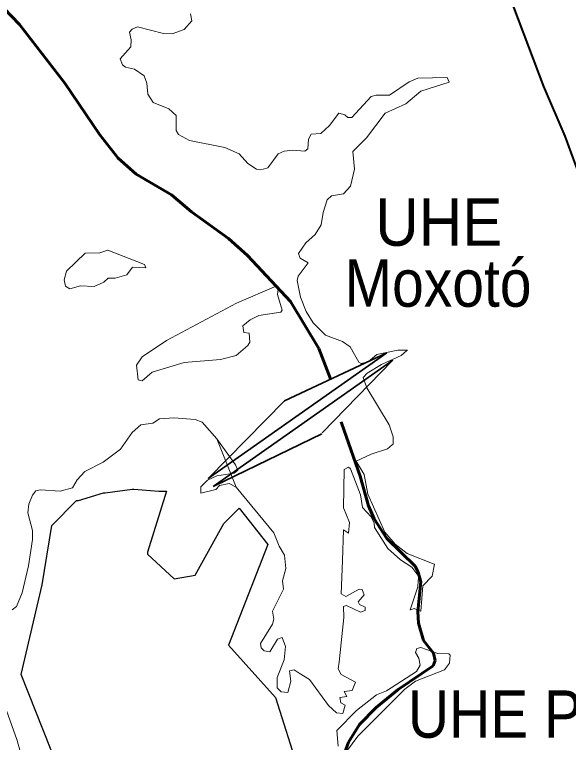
# Model space of a CAD drawing. Extents: x 553962 to 842807, y 8883888 to 9032388.
# Drawn here: x 584093 to 589939, y 8960655 to 8968341 of the extents above; entities that cross this region are included whole.
import ezdxf
from ezdxf.enums import TextEntityAlignment as Align

# ---------------------------------------------------------------- set-up
doc = ezdxf.new("R2010")
doc.units = 0
doc.header["$LTSCALE"] = 200
doc.linetypes.add('LONG_DASH_SHORT_DASH', pattern=[9.9, 6, -1.2, 1.5, -1.2])
for name, color, linetype, lineweight in [('12', 7, 'Continuous', 25), ('21', 7, 'Continuous', 25), ('25', 7, 'Continuous', 13), ('7', 7, 'LONG_DASH_SHORT_DASH', 60)]:
    doc.layers.add(name, color=color, linetype=linetype, lineweight=lineweight)
doc.layers.add('42', color=7, linetype='Continuous')

msp = doc.modelspace()

# ---------------------------------------------------------------- linework, layer by layer
at = {"layer": '12', "lineweight": 40}
msp.add_lwpolyline([(589251, 8968710.7), (589674.6, 8967582.3), (589899.5, 8967058.9), (590052.2, 8966645.4), (590154.6, 8966267.7), (590247.4, 8965995.5), (590238.8, 8965878.8), (590381.4, 8965077.2), (590437.7, 8964620.9), (590556.9, 8963909.5), (590712.3, 8962804.7), (590781.8, 8962609.4), (591396.4, 8961227.9)], dxfattribs=at)
at = {"layer": '21'}
msp.add_lwpolyline([(584626.8, 8960201.4), (584162.8, 8961372.1), (584384.7, 8962320.7), (584485.6, 8962946.4), (584747.9, 8963208.8), (584768.1, 8963208.8), (585030.4, 8963289.5), (585050.6, 8963289.5), (585333, 8963329.9), (585353.2, 8963329.9), (585615.5, 8963309.7), (585655.9, 8963309.7), (585676, 8963309.7), (585696.2, 8963309.7), (585494.5, 8962663.8), (585494.5, 8962643.7), (585776.9, 8962381.3), (585998.9, 8962421.6), (586301.5, 8962966.6), (586463, 8963128.1), (586765.6, 8962744.6), (586351.3, 8961682.2), (586846.3, 8961129.9), (587088.5, 8960362.9)], dxfattribs=at)
at = {"layer": '25', "lineweight": 35}
for p, q in [((588022.6, 8964770.6), (586135.6, 8963442.6)), ((586940.7, 8964263.4), (588022.6, 8964770.6)), ((588084.7, 8964692), (586189.9, 8963358.5)), ((587339.3, 8963925.5), (588084.7, 8964692)), ((586940.7, 8964263.4), (586135.6, 8963442.6)), ((586189.9, 8963358.5), (587335.7, 8963913.8))]:
    msp.add_line(p, q, dxfattribs=at)
at = {"layer": '25'}
for points in [[(585950.2, 8968348.5), (585965.4, 8968274.1), (585883, 8968184.3), (585757.4, 8968137.5), (585664, 8968141.7), (585392.1, 8968211.7), (585332.8, 8968188.5), (585307.1, 8968156.3), (585324, 8968076.1), (585319.8, 8967999.4)], [(585950.2, 8968348.5), (585965.4, 8968274.1), (585883, 8968184.3), (585757.4, 8968137.5), (585664, 8968141.7), (585392.1, 8968211.7), (585332.8, 8968188.5), (585307.1, 8968156.3), (585324, 8968076.1), (585319.8, 8967999.4)], [(585319.8, 8967999.4), (585209.4, 8967874), (585230.7, 8967810.4), (585264.6, 8967784.9), (585358.3, 8967763.5), (585460, 8967695.5), (585487.7, 8967616.8), (585500.5, 8967502.3), (585557.8, 8967413.1), (585721.3, 8967347.2), (585797.8, 8967276.9), (585799.9, 8967116.4), (585821.7, 8967075), (585940.4, 8967011.6), (586314, 8966937.2), (586464.8, 8966869.3), (586554.2, 8966767.2), (586645.4, 8966710), (586692.1, 8966701.5), (586766.2, 8966722.7), (586877, 8966869.2), (586938.3, 8966898.9), (587031.7, 8966909.6), (587155.3, 8966899.2), (587187, 8966922.6), (587195.6, 8967026.5), (587225.2, 8967079.4), (587325, 8967083.9), (587416.4, 8967171), (587516.5, 8967298.4), (587577.2, 8967281.7), (587609.8, 8967253.9), (587652.2, 8967256), (587856.2, 8967474.6), (587908.7, 8967491.8), (588049.3, 8967489.5), (588259.2, 8967631.5), (588349.7, 8967670.3), (588657.3, 8967677.5), (588667.8, 8967651.8)], [(585319.8, 8967999.4), (585209.4, 8967874), (585230.7, 8967810.4), (585264.6, 8967784.9), (585358.3, 8967763.5), (585460, 8967695.5), (585487.7, 8967616.8), (585500.5, 8967502.3), (585557.8, 8967413.1), (585721.3, 8967347.2), (585797.8, 8967276.9), (585799.9, 8967116.4), (585821.7, 8967075), (585940.4, 8967011.6), (586314, 8966937.2), (586464.8, 8966869.3), (586554.2, 8966767.2), (586645.4, 8966710), (586692.1, 8966701.5), (586766.2, 8966722.7), (586877, 8966869.2), (586938.3, 8966898.9), (587031.7, 8966909.6), (587155.3, 8966899.2), (587187, 8966922.6), (587195.6, 8967026.5), (587225.2, 8967079.4), (587325, 8967083.9), (587416.4, 8967171), (587516.5, 8967298.4), (587577.2, 8967281.7), (587609.8, 8967253.9), (587652.2, 8967256), (587856.2, 8967474.6), (587908.7, 8967491.8), (588049.3, 8967489.5), (588259.2, 8967631.5), (588349.7, 8967670.3), (588657.3, 8967677.5), (588667.8, 8967651.8)], [(588667.8, 8967651.8), (588678.2, 8967626.5), (588381.1, 8967532.1), (588221.7, 8967398.4), (588005.1, 8967300.6), (587807.3, 8967041.3), (587663.1, 8966894.9), (587682, 8966707.8), (587637.4, 8966529.4), (587563.2, 8966446.7), (587438, 8966427.4), (587392.7, 8966384.2), (587348.6, 8966249.6), (587329.2, 8966121.3), (587265.6, 8966019.6), (587165.8, 8965932.5), (587089.5, 8965818), (587106.5, 8965769), (587193.3, 8965719.9), (587087.2, 8965577.5), (587074.5, 8965534.6), (587110.7, 8965356.6), (587170.4, 8965207.5), (587244.3, 8965087.2), (587376.1, 8964957.5), (587554.3, 8964887.4), (587635.2, 8964832.1), (587726.7, 8964670.8), (587750.6, 8964658), (587826.4, 8964675), (587917.9, 8964751.3), (588138.8, 8964796.3), (588239.8, 8964798.6), (588239.8, 8964798.6), (588231, 8964790.9)], [(588667.8, 8967651.8), (588678.2, 8967626.5), (588381.1, 8967532.1), (588221.7, 8967398.4), (588005.1, 8967300.6), (587807.3, 8967041.3), (587663.1, 8966894.9), (587682, 8966707.8), (587637.4, 8966529.4), (587563.2, 8966446.7), (587438, 8966427.4), (587392.7, 8966384.2), (587348.6, 8966249.6), (587329.2, 8966121.3), (587265.6, 8966019.6), (587165.8, 8965932.5), (587089.5, 8965818), (587106.5, 8965769), (587193.3, 8965719.9), (587087.2, 8965577.5), (587074.5, 8965534.6), (587110.7, 8965356.6), (587170.4, 8965207.5), (587244.3, 8965087.2), (587376.1, 8964957.5), (587554.3, 8964887.4), (587635.2, 8964832.1), (587678.5, 8964757.6)], [(588231, 8964790.9), (588174.2, 8964740.5), (587964.7, 8964647.4), (587813.9, 8964556), (587773.6, 8964509.6), (587809.5, 8964400.9), (588045.3, 8964009.8), (588090.5, 8963883.4), (588087.9, 8963805.8), (588079.5, 8963798.7)], [(587773.6, 8964509.6), (587809.5, 8964400.9), (588045.3, 8964009.8), (588090.5, 8963883.4), (588087.9, 8963805.8), (588079.5, 8963798.7)], [(587098.4, 8961386.8), (587045, 8961420.4), (586993.8, 8961411.8), (587008.6, 8961303.5), (586976.2, 8961182.7), (586906.7, 8961189.1), (586864.3, 8961233.5), (586864.2, 8961341.7), (586938.6, 8961529.2), (586953.1, 8961669.7), (586916.8, 8961762.6), (586868.3, 8961747.5), (586787.2, 8961611.7), (586725.9, 8961622.5), (586694.3, 8961654.3), (586687.9, 8961700.7), (586815.2, 8961902.8), (586830.2, 8961956.5), (586815.4, 8962043.2), (586930, 8962273.3), (586921.5, 8962361.5), (586957.6, 8962493.3), (586943, 8962632.7), (586885.4, 8962727), (586830, 8962867.4), (586432.9, 8963349.4), (586358.6, 8963389.7), (586254.6, 8963368.5), (586216.2, 8963326.1), (586059.1, 8963288.1), (586058.9, 8963353.2), (586131.1, 8963423.6), (586229.2, 8963469.6), (586410.8, 8963500), (586449.8, 8963530), (586424.4, 8963587.3), (586226.9, 8963861.3), (586073.9, 8964035.5), (585999.3, 8964065.2), (585774.7, 8964084.4), (585623.6, 8964071.6), (585553.5, 8964025), (585426.1, 8964010), (585334.9, 8963929.5), (585211.3, 8963752.8), (585026.9, 8963615.1), (584835.5, 8963515.1), (584755, 8963428.2), (584703.5, 8963345.2), (584575.7, 8963306.9), (584575.7, 8963306.9), (584367.9, 8963323.8), (584319.4, 8963311.1), (584283.8, 8963267.3), (584244.9, 8963172.8), (584232.2, 8963079.6), (584283.2, 8962892.7), (584283.2, 8962799.2), (584240.7, 8962518.8), (584172.1, 8962236.3), (584113.2, 8962091.9), (584066.4, 8962055.5)], [(587098.4, 8961386.8), (587045, 8961420.4), (586993.8, 8961411.8), (587008.6, 8961303.5), (586976.2, 8961182.7), (586906.7, 8961189.1), (586864.3, 8961233.5), (586864.2, 8961341.7), (586938.6, 8961529.2), (586953.1, 8961669.7), (586916.8, 8961762.6), (586868.3, 8961747.5), (586787.2, 8961611.7), (586725.9, 8961622.5), (586694.3, 8961654.3), (586687.9, 8961700.7), (586815.2, 8961902.8), (586830.2, 8961956.5), (586815.4, 8962043.2), (586930, 8962273.3), (586921.5, 8962361.5), (586957.6, 8962493.3), (586943, 8962632.7), (586885.4, 8962727), (586830, 8962867.4), (586432.9, 8963349.4), (586226.9, 8963861.3), (586073.9, 8964035.5), (585999.3, 8964065.2), (585774.7, 8964084.4), (585623.6, 8964071.6), (585553.5, 8964025), (585426.1, 8964010), (585334.9, 8963929.5), (585211.3, 8963752.8), (585026.9, 8963615.1), (584835.5, 8963515.1), (584755, 8963428.2), (584703.5, 8963345.2), (584575.7, 8963306.9), (584575.7, 8963306.9), (584367.9, 8963323.8), (584319.4, 8963311.1), (584283.8, 8963267.3), (584244.9, 8963172.8), (584232.2, 8963079.6), (584283.2, 8962892.7), (584283.2, 8962799.2), (584240.7, 8962518.8), (584172.1, 8962236.3), (584113.2, 8962091.9), (584066.4, 8962055.5)], [(588079.5, 8963798.7), (588030.2, 8963757.2), (587858.5, 8963700), (587699.1, 8963625.3), (587781.9, 8963483), (587820, 8963275.3), (588002, 8962877.1), (588002, 8962877.1), (588108.8, 8962750.5), (588236.2, 8962650.7), (588523, 8962536.8)], [(588079.5, 8963798.7), (588030.2, 8963757.2), (587858.5, 8963700), (587699.1, 8963625.3), (587781.9, 8963483), (587820, 8963275.3), (588002, 8962877.1), (588002, 8962877.1), (588108.8, 8962750.5), (588236.2, 8962650.7), (588523, 8962536.8)], [(587982.8, 8962779.3), (587890.3, 8962924.4), (587890.1, 8962969.1), (587856.3, 8963036.9), (587766.9, 8963135.1), (587743.6, 8963270.8), (587637.1, 8963543.2), (587617, 8963563.8), (587571.7, 8963538.4), (587565.1, 8963131.3), (587628.8, 8962977.9), (587616.1, 8962866.9), (587565.4, 8962902.1), (587554.1, 8962576.4)], [(587982.8, 8962779.3), (587890.3, 8962924.4), (587890.1, 8962969.1), (587856.3, 8963036.9), (587766.9, 8963135.1), (587743.6, 8963270.8), (587637.1, 8963543.2), (587617, 8963563.8), (587571.7, 8963538.4), (587565.1, 8963131.3), (587628.8, 8962977.9), (587616.1, 8962866.9), (587565.4, 8962902.1), (587554.1, 8962576.4)], [(588354.5, 8962361.1), (588359.4, 8962408.8), (588285.5, 8962505.9), (588167, 8962584.2), (588032.3, 8962701.8), (587982.8, 8962779.3)], [(588354.5, 8962361.1), (588359.4, 8962408.8), (588285.5, 8962505.9), (588167, 8962584.2), (588032.3, 8962701.8), (587982.8, 8962779.3)], [(587554.1, 8962576.4), (587541.8, 8962223.9), (587588.7, 8962196), (587730.7, 8962272.2), (587762.7, 8962269), (587781.7, 8962215.1)], [(587554.1, 8962576.4), (587541.8, 8962223.9), (587588.7, 8962196), (587730.7, 8962272.2), (587762.7, 8962269), (587781.7, 8962215.1)], [(588523, 8962536.8), (588524.4, 8962536.2), (588501.9, 8962412.8), (588402.2, 8962308.3), (588381.1, 8962040.8), (588376.4, 8962042.8)], [(588523, 8962536.8), (588524.4, 8962536.2), (588501.9, 8962412.8), (588402.2, 8962308.3), (588381.1, 8962040.8), (588376.4, 8962042.8)], [(588271.6, 8962055.8), (588270.1, 8962055.2), (588348.1, 8962299.3), (588354.5, 8962361.1)], [(588271.6, 8962055.8), (588270.1, 8962055.2), (588348.1, 8962299.3), (588354.5, 8962361.1)], [(587781.7, 8962215.1), (587781.7, 8962215.1), (587718.2, 8962140.9), (587735, 8962113.3), (587792.4, 8962083.3), (587794.6, 8962050), (587745.5, 8962032.4), (587597.2, 8962100.2), (587563.1, 8962089.5), (587569.5, 8961975.7), (587540.2, 8961707.3), (587517.7, 8961501.6)], [(587781.7, 8962215.1), (587781.7, 8962215.1), (587718.2, 8962140.9), (587735, 8962113.3), (587792.4, 8962083.3), (587794.6, 8962050), (587745.5, 8962032.4), (587597.2, 8962100.2), (587563.1, 8962089.5), (587569.5, 8961975.7), (587540.2, 8961707.3), (587517.7, 8961501.6)], [(588376.4, 8962042.8), (588311.2, 8962069.4), (588271.6, 8962055.8), (588271.7, 8962060.3), (588271.6, 8962055.8)], [(588376.4, 8962042.8), (588311.2, 8962069.4), (588271.6, 8962055.8), (588271.7, 8962060.3), (588271.6, 8962055.8)], [(587596.7, 8960558.6), (587717.4, 8960723.2), (588213.5, 8961217.2), (588323.7, 8961300.9), (588630.6, 8961421.7), (588681.9, 8961493.8), (588689.2, 8961575.7), (588675.2, 8961590.7), (588561, 8961592.8), (588381.1, 8961656.2), (588338.6, 8961648.6), (588325.4, 8961606.6), (588359, 8961544.8), (588373.9, 8961471.3), (588335.7, 8961403.9), (588018, 8961201.6), (587911.6, 8961156.7), (587701, 8960992.4), (587493.3, 8960783.2), (587506.9, 8960616.2)], [(587517.7, 8961501.6), (587510, 8961431.2), (587539.9, 8961371.6), (587692.7, 8961292.6), (587670.8, 8961239.2)], [(587517.7, 8961501.6), (587510, 8961431.2), (587539.9, 8961371.6), (587692.7, 8961292.6), (587670.8, 8961239.2)], [(587670.8, 8961239.2), (587656.4, 8961204.1), (587570.6, 8961194.6), (587599.2, 8961141.8), (587527.1, 8961129.4), (587535.4, 8961074.6), (587582.5, 8961050.1), (587556.1, 8960961.2), (587491.1, 8960968.1), (587408.1, 8961044.4), (587205.3, 8961319.5), (587098.4, 8961386.8)], [(587670.8, 8961239.2), (587656.4, 8961204.1), (587570.6, 8961194.6), (587599.2, 8961141.8), (587527.1, 8961129.4), (587535.4, 8961074.6), (587582.5, 8961050.1), (587556.1, 8960961.2), (587491.1, 8960968.1), (587408.1, 8961044.4), (587205.3, 8961319.5), (587098.4, 8961386.8)], [(584009.2, 8960993.4), (584121.2, 8960674.7), (584187.7, 8960432.6)], [(584009.2, 8960993.4), (584121.2, 8960674.7), (584187.7, 8960432.6)]]:
    msp.add_lwpolyline(points, dxfattribs=at)
for points in [[(585077.7, 8965854), (584992.7, 8965826.3), (584839.9, 8965820.3), (584642.3, 8965632.9), (584616.8, 8965540.1), (584629.5, 8965471.6), (584675.9, 8965446), (584789, 8965475.7), (584933.4, 8965469.6), (585035.3, 8965516.3), (585079.8, 8965558.5), (585154.1, 8965558.7), (585279.1, 8965592.6), (585337.4, 8965673.5), (585478.9, 8965666.9), (585463.8, 8965703.2)], [(585077.7, 8965854), (584992.7, 8965826.3), (584839.9, 8965820.3), (584642.3, 8965632.9), (584616.8, 8965540.1), (584629.5, 8965471.6), (584675.9, 8965446), (584789, 8965475.7), (584933.4, 8965469.6), (585035.3, 8965516.3), (585079.8, 8965558.5), (585154.1, 8965558.7), (585279.1, 8965592.6), (585337.4, 8965673.5), (585478.9, 8965666.9), (585463.8, 8965703.2)], [(585439, 8964728.2), (585379.4, 8964639), (585398.5, 8964484), (585440.9, 8964473.3), (585545, 8964564.5), (585884.6, 8964666.3), (586267.5, 8964700.5), (586430.8, 8964740.8), (586553.9, 8964845), (586575.2, 8964881), (586570.7, 8964976.5), (586513.6, 8964985.3), (586501.3, 8965053.3), (586579.7, 8965116.9), (586670.6, 8965163.4), (586903.9, 8965197.4), (586919.2, 8965218.6), (586866.7, 8965384.8), (586876.8, 8965441.6), (586860, 8965477.5), (586435.1, 8965293.1), (585696.3, 8964900.4)], [(585439, 8964728.2), (585379.4, 8964639), (585398.5, 8964484), (585440.9, 8964473.3), (585545, 8964564.5), (585884.6, 8964666.3), (586267.5, 8964700.5), (586430.8, 8964740.8), (586553.9, 8964845), (586575.2, 8964881), (586570.7, 8964976.5), (586513.6, 8964985.3), (586501.3, 8965053.3), (586579.7, 8965116.9), (586670.6, 8965163.4), (586903.9, 8965197.4), (586919.2, 8965218.6), (586866.7, 8965384.8), (586876.8, 8965441.6), (586860, 8965477.5), (586435.1, 8965293.1), (585696.3, 8964900.4)]]:
    msp.add_lwpolyline(points, close=True, dxfattribs=at)
at = {"layer": '7'}
for points in [[(583174.4, 8969966), (583327.9, 8969505.4), (583474.7, 8969160.4), (583725.5, 8968684.8), (583883.2, 8968539.9), (583982.9, 8968403.5), (584146.9, 8968235.1), (584624.8, 8967616.6), (584992.2, 8967072.1), (585186.8, 8966825.7), (585377.2, 8966655.9), (585748.8, 8966438.6), (585960.5, 8966257.3), (586351.6, 8965976.8), (586551, 8965796.4), (587006.6, 8965310.9), (587303.1, 8964815.2), (587426.7, 8964495.3)], [(587540.9, 8964040.5), (587545.5, 8964019), (587739.9, 8963466), (587828.5, 8963155), (587886.8, 8963016.8), (588023, 8962809.1), (588321.3, 8962515.1), (588353.7, 8962454.8), (588379.7, 8962350), (588349.5, 8962039.7), (588356.1, 8961913.4), (588409.9, 8961732.7), (588515.9, 8961598.5), (588533, 8961520.2), (588511.4, 8961464.3), (588140, 8961216), (587908.2, 8961023.1), (587733.4, 8960846.2), (587616.5, 8960660), (587498.3, 8960337.4), (587362.2, 8959603), (587314, 8959147.2), (587303.2, 8958935.8), (587310.7, 8958873)]]:
    msp.add_lwpolyline(points, dxfattribs=at)

# ---------------------------------------------------------------- texts
at = {"layer": '42'}
for s, width, p in [('UHE', 0.95, (588571.1, 8965899.4)), ('Moxotó', 0.9, (588562.6, 8965256.2)), ('UHE PA', 0.9, (589364.5, 8960705))]:
    msp.add_text(s, height=500, dxfattribs=dict(at, width=width)).set_placement(p, align=Align.CENTER)

doc.saveas('drawing.dxf')
